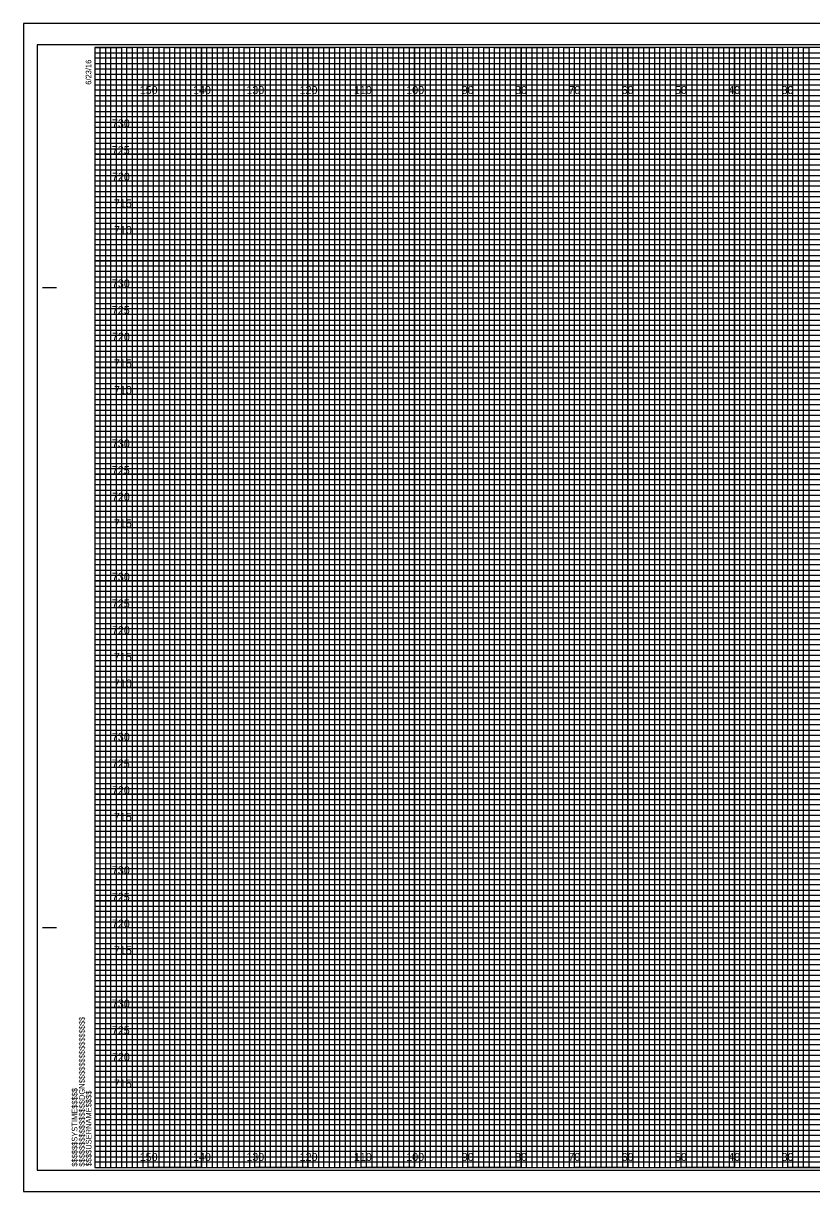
# Model space of a CAD drawing. Extents: x -13 to 323, y -5 to 434.
# Drawn here: x -13.4 to 134.5, y -4.5 to 214.5 of the extents above; entities that cross this region are included whole.
import ezdxf

# ---------------------------------------------------------------- set-up
doc = ezdxf.new("R2010")
doc.units = 0
for name, color, linetype in [('Exist Cross Section Cell', 7, 'Continuous'), ('Prop CMT Pvmt Course 1', 7, 'Continuous'), ('Prop CMT Pvmt Course 2', 7, 'Continuous'), ('Prop CMT Pvmt Course 3', 7, 'Continuous'), ('Prop CMT Pvmt Surface Shoulder', 7, 'Continuous'), ('Prop CMT Shld Paved Course 1', 7, 'Continuous'), ('Prop CMT Shld Paved Course 2', 7, 'Continuous'), ('Prop CMT Shld Paved Course 3', 7, 'Continuous'), ('Prop CMT Slope Grass', 7, 'Continuous'), ('Prop CMT Subgrade Earthwork', 7, 'Continuous'), ('Scratch_Level_1', 7, 'Continuous')]:
    doc.layers.add(name, color=color, linetype=linetype)

msp = doc.modelspace()

# ---------------------------------------------------------------- linework, layer by layer
at = {"layer": 'Prop CMT Pvmt Course 1'}
msp.add_lwpolyline([(-10.8, -0.5), (322.4, -0.5), (322.4, 210.5), (-10.8, 210.5)], close=True, dxfattribs=at)
at = {"layer": 'Prop CMT Pvmt Course 2'}
for p, q in [((10, 0), (10, 210)), ((20, 0), (20, 210)), ((30, 0), (30, 210)), ((40, 0), (40, 210)), ((50, 0), (50, 210)), ((60, 0), (60, 210)), ((70, 0), (70, 210)), ((80, 0), (80, 210)), ((90, 0), (90, 210)), ((100, 0), (100, 210)), ((110, 0), (110, 210)), ((120, 0), (120, 210)), ((130, 0), (130, 210)), ((0, 200), (320, 200)), ((0, 190), (320, 190)), ((0, 180), (320, 180)), ((0, 170), (320, 170)), ((0, 160), (320, 160)), ((0, 150), (320, 150)), ((0, 140), (320, 140)), ((0, 130), (320, 130)), ((0, 120), (320, 120)), ((0, 110), (320, 110)), ((0, 100), (320, 100)), ((0, 90), (320, 90)), ((0, 80), (320, 80)), ((0, 70), (320, 70)), ((0, 60), (320, 60)), ((0, 50), (320, 50)), ((0, 40), (320, 40)), ((0, 30), (320, 30)), ((0, 20), (320, 20)), ((0, 10), (320, 10))]:
    msp.add_line(p, q, dxfattribs=at)
at = {"layer": 'Prop CMT Pvmt Course 3'}
for p, q in [((323.3, 214.5), (-13.4, 214.5)), ((-13.4, 214.5), (-13.4, -4.5)), ((-13.4, -4.5), (323.3, -4.5))]:
    msp.add_line(p, q, dxfattribs=at)
at = {"layer": 'Prop CMT Pvmt Surface Shoulder'}
msp.add_lwpolyline([(-13.4, -4.5), (323.3, -4.5), (323.3, 214.5), (-13.4, 214.5)], close=True, dxfattribs=at)
at = {"layer": 'Prop CMT Shld Paved Course 1'}
for points in [[(0, 210), (5, 210), (5, 0), (15, 0), (15, 210), (25, 210), (25, 0), (35, 0), (35, 210), (45, 210), (45, 0), (55, 0), (55, 210), (65, 210), (65, 0), (75, 0), (75, 210), (85, 210), (85, 0), (95, 0), (95, 210), (105, 210), (105, 0), (115, 0), (115, 210), (125, 210), (125, 0), (135, 0)], [(0, 205), (275, 205)], [(0, 185), (320, 185), (320, 195), (0, 195)], [(0, 165), (320, 165), (320, 175), (0, 175)], [(0, 145), (320, 145), (320, 155), (0, 155)], [(0, 125), (320, 125), (320, 135), (0, 135)], [(0, 105), (320, 105), (320, 115), (0, 115)], [(0, 85), (320, 85), (320, 95), (0, 95)], [(0, 65), (320, 65), (320, 75), (0, 75)], [(0, 45), (320, 45), (320, 55), (0, 55)], [(0, 25), (320, 25), (320, 35), (0, 35)], [(0, 5), (320, 5), (320, 15), (0, 15)]]:
    msp.add_lwpolyline(points, dxfattribs=at)
at = {"layer": 'Prop CMT Shld Paved Course 2'}
for p, q in [((0, 209), (260, 209)), ((260, 207.98), (0, 207.98)), ((0, 207.98), (0, 207)), ((0, 207), (260, 207)), ((260, 205.89), (0, 205.89)), ((0, 205.89), (0, 204)), ((0, 204), (320, 204))]:
    msp.add_line(p, q, dxfattribs=at)
for points in [[(0, 203), (270, 203), (320, 203), (320, 202), (0, 202)], [(0, 201), (320, 201), (320, 199), (0, 199)], [(0, 198), (320, 198), (320, 197), (0, 196.98)], [(0, 196), (320, 196), (320, 194), (0, 194)], [(0, 193), (320, 193), (320, 192), (0, 192)], [(0, 191), (320, 191), (320, 189), (0, 189)], [(0, 188), (320, 188), (320, 187), (0, 187)], [(0, 186), (320, 186), (320, 184), (0, 184)], [(0, 183), (320, 183), (320, 182), (0, 182)], [(0, 181), (320, 181), (320, 179), (0, 179)], [(0, 178), (320, 178), (320, 177), (0, 177)], [(0, 176), (320, 176), (320, 173.95), (320, 173), (320, 172), (0, 172)], [(0, 174), (320, 174), (320, 173), (0, 173)], [(0, 171), (320, 171), (320, 169), (0, 169.03)], [(0, 169.03), (320, 169), (320, 168), (0, 168)], [(0, 167), (320, 167), (320, 166), (0, 166)], [(0, 164), (320, 164), (320, 163), (0, 163)], [(0, 162), (320, 162), (320, 161), (0, 161)], [(-0.07, 158.89), (320, 158.89), (320, 157.88), (-0.07, 157.88)], [(0, 157), (320, 157), (320, 156), (0, 156)], [(0, 154), (320, 154), (320, 153), (0, 153)], [(0, 152), (320, 152), (320, 151), (0, 151)], [(0, 149), (320, 149), (320, 148), (0, 148)], [(0, 147), (320, 147), (320, 146), (0, 146)], [(0, 144), (320, 144), (320, 143), (0, 143)], [(0, 142), (320, 142), (320, 141), (0, 141)], [(0, 139), (320, 139), (319.99, 137.98), (0, 138)], [(0, 137), (320, 137), (320, 136), (0, 136)], [(0, 134), (320, 134), (320, 133), (0, 133)], [(0, 132), (320, 132), (320, 131), (0, 131)], [(0, 129), (320, 129), (320, 128), (0, 128)], [(0, 127), (320, 127), (320, 126), (0, 126)], [(0, 124), (320, 124), (320, 123), (0, 123)], [(0, 122), (320, 122), (320, 121), (0, 121)], [(0, 119), (320, 119), (320, 118), (0, 118)], [(0, 116.99), (320.07, 116.91), (320, 116), (0, 116)], [(0, 114), (320, 114), (320, 113), (0, 113)], [(0, 112), (320, 112), (320, 111), (0, 111)], [(0, 109), (320, 109), (320, 108), (0, 108)], [(0, 107), (320, 107), (320, 106), (0, 106)], [(0, 104), (320, 104), (320, 103), (0, 103)], [(0, 102), (320, 102), (320, 101), (0, 101)], [(0, 99), (320, 99), (320, 98), (0, 98)], [(0, 97), (320, 97), (320, 96), (0, 96)], [(0, 94), (320, 94), (320, 93), (0, 93)], [(0, 92), (320, 92), (320, 91), (0, 91)], [(0, 89), (320, 89), (320, 88), (0, 88)], [(0, 87), (320, 87), (320, 86), (0, 86)], [(0, 84), (320, 84), (320, 83), (0, 83)], [(0, 82), (320, 82), (320, 81), (0, 81)], [(0, 79), (320, 79), (319.99, 77.98), (0, 78)], [(0, 77), (320, 77), (320, 76), (0, 76)], [(0, 74), (320, 74), (320, 73), (0, 73)], [(0, 72), (320, 72), (320, 71), (0, 71)], [(0, 69), (320, 69), (320, 68), (0, 68)], [(0, 67), (320, 67), (320, 66), (0, 66)], [(0, 64), (320, 64), (320, 63), (0, 63)], [(0, 62), (320, 62), (320, 61), (0, 61)], [(0, 59), (320, 59), (320, 58), (0, 58)], [(0, 56.99), (320.07, 56.91), (320, 56), (0, 56)], [(0, 54), (320, 54), (320, 53), (0, 53)], [(0, 52), (320, 52), (320, 51), (0, 51)], [(0, 49), (320, 49), (320, 48), (0, 48)], [(0, 47), (320, 47), (320, 46), (0, 46)], [(0, 44), (320, 44), (320, 43), (0, 43)], [(0, 42), (320, 42), (320, 41), (0, 41)], [(0, 39), (320, 39), (320, 38), (0, 38)], [(0, 37), (320, 37), (320, 36), (0, 36)], [(0, 34), (320, 34), (320, 33), (0, 33)], [(0, 32), (320, 32), (320, 31), (0, 31)], [(0, 29), (320, 29), (320, 28), (0, 28)], [(0, 27), (320, 27), (320, 26), (0, 26)], [(0, 24), (320, 24), (320, 23), (0, 23)], [(0, 22), (320, 22), (320, 21), (0, 21)], [(0, 19), (320, 19), (320, 18), (0, 18)], [(0, 17), (320, 17), (320, 16), (0, 16)], [(0, 14), (320, 14), (320, 13), (0, 13)], [(0, 12), (320, 12), (320, 11), (0, 11)], [(0, 9), (320, 9), (320, 8), (0, 8)], [(0, 7), (320, 7), (320, 6), (0, 6)], [(0, 4), (320, 4), (320, 3), (0, 3)], [(0, 2), (320, 2), (320, 1), (0, 1)]]:
    msp.add_lwpolyline(points, dxfattribs=at)
at = {"layer": 'Prop CMT Shld Paved Course 3'}
for p, q in [((-9.8, 165), (-7.3, 165)), ((-9.7, 165), (-7.2, 165)), ((-9.8, 45), (-7.3, 45)), ((-9.7, 45), (-7.2, 45)), ((0, 0), (0, 0)), ((0, 0), (0, 0)), ((0, 0), (0, 0)), ((0, 0), (0, 0)), ((0, 0), (0, 0)), ((0, 0), (0, 0)), ((0, 0), (0, 0))]:
    msp.add_line(p, q, dxfattribs=at)
msp.add_lwpolyline([(320, 210), (0, 210), (0, 0), (320, 0)], close=True, dxfattribs=at)
at = {"layer": 'Prop CMT Subgrade Earthwork'}
for points in [[(0, 0), (1, 0), (1, 210), (2, 210), (2, 0)], [(2, 0), (3, 0), (3, 210), (4, 210), (4, 0)], [(5, 0), (6, 0), (6, 210), (7, 210), (7, 0)], [(7, 0), (8, 0), (8, 210), (9, 210), (9, 0)], [(10, 0), (11, 0), (11, 210), (12, 210), (12, 0)], [(12, 0), (13, 0), (13, 210), (14, 210), (14, 0)], [(15, 0), (16, 0), (16, 210), (17, 210), (17, 0)], [(17, 0), (18, 0), (18, 210), (19, 210), (19, 0)], [(20, 0), (21, 0), (21, 210), (22, 210), (22, 0)], [(22, 0), (23, 0), (23, 210), (24, 210), (24, 0)], [(25, 0), (26, 0), (26, 210), (27, 210), (27, 0)], [(27, 0), (28, 0), (28, 210), (29, 210), (29, 0)], [(30, 0), (31, 0), (31, 210), (32, 210), (32, 0)], [(32, 0), (33, 0), (33, 210), (34, 210), (34, 0)], [(35, 0), (36, 0), (36, 210), (37, 210), (37, 0)], [(37, 0), (38, 0), (38, 210), (39, 210), (39, 0)], [(40, 0), (41, 0), (41, 210), (42, 210), (42, 0)], [(42, 0), (43, 0), (43, 210), (44, 210), (44, 0)], [(45, 0), (46, 0), (46, 210), (47, 210), (47, 0)], [(47, 0), (48, 0), (48, 210), (49, 210), (49, 0)], [(50, 0), (51, 0), (51, 210), (52, 210), (52, 0)], [(52, 0), (53, 0), (53, 210), (54, 210), (54, 0)], [(55, 0), (56, 0), (56, 210), (57, 210), (57, 0)], [(57, 0), (58, 0), (58, 210), (59, 210), (59, 0)], [(60, 0), (61, 0), (61, 210), (62, 210), (62, 0)], [(62, 0), (63, 0), (63, 210), (64, 210), (64, 0)], [(65, 0), (66, 0), (66, 210), (67, 210), (67, 0)], [(67, 0), (68, 0), (68, 210), (69, 210), (69, 0)], [(70, 0), (71, 0), (71, 210), (72, 210), (72, 0)], [(72, 0), (73, 0), (73, 210), (74, 210), (74, 0)], [(75, 0), (76, 0), (76, 210), (77, 210), (77, 0)], [(77, 0), (78, 0), (78, 210), (79, 210), (79, 0)], [(80, 0), (81, 0), (81, 210), (82, 210), (82, 0)], [(82, 0), (83, 0), (83, 210), (84, 210), (84, 0)], [(85, 0), (86, 0), (86, 210), (87, 210), (87, 0)], [(87, 0), (88, 0), (88, 210), (89, 210), (89, 0)], [(90, 0), (91, 0), (91, 210), (92, 210), (92, 0)], [(92, 0), (93, 0), (93, 210), (94, 210), (94, 0)], [(95, 0), (96, 0), (96, 210), (97, 210), (97, 0)], [(97, 0), (98, 0), (98, 210), (99, 210), (99, 0)], [(100, 0), (101, 0), (101, 210), (102, 210), (102, 0)], [(102, 0), (103, 0), (103, 210), (104, 210), (104, 0)], [(105, 0), (106, 0), (106, 210), (107, 210), (107, 0)], [(107, 0), (108, 0), (108, 210), (109, 210), (109, 0)], [(110, 0), (111, 0), (111, 210), (112, 210), (112, 0)], [(112, 0), (113, 0), (113, 210), (114, 210), (114, 0)], [(115, 0), (116, 0), (116, 210), (117, 210), (117, 0)], [(117, 0), (118, 0), (118, 210), (119, 210), (119, 0)], [(120, 0), (121, 0), (121, 210), (122, 210), (122, 0)], [(122, 0), (123, 0), (123, 210), (124, 210), (124, 0)], [(125, 0), (126, 0), (126, 210), (127, 210), (127, 0)], [(127, 0), (128, 0), (128, 210), (129, 210), (129, 0)], [(130, 0), (131, 0), (131, 210), (132, 210), (132, 0)], [(132, 0), (133, 0), (133, 210), (134, 210), (134, 0)]]:
    msp.add_lwpolyline(points, dxfattribs=at)
at = {"layer": 'Scratch_Level_1'}
for p, q in [((10, 210), (0, 210)), ((10, 0), (10, 210)), ((30, 210), (20, 210)), ((20, 210), (20, 0)), ((30, 0), (30, 210)), ((50, 210), (40, 210)), ((40, 210), (40, 0)), ((50, 0), (50, 210)), ((70, 210), (60, 210)), ((60, 210), (60, 0)), ((70, 0), (70, 210)), ((90, 210), (80, 210)), ((80, 210), (80, 0)), ((90, 0), (90, 210)), ((110, 210), (100, 210)), ((100, 210), (100, 0)), ((110, 0), (110, 210)), ((130, 210), (120, 210)), ((120, 210), (120, 0)), ((130, 0), (130, 210)), ((20, 0), (10, 0)), ((40, 0), (30, 0)), ((60, 0), (50, 0)), ((80, 0), (70, 0)), ((100, 0), (90, 0)), ((120, 0), (110, 0)), ((140, 0), (130, 0))]:
    msp.add_line(p, q, dxfattribs=at)
for points in [[(0, 200), (320, 200), (320, 190), (0, 190)], [(0, 180), (320, 180), (320, 170), (0, 170)], [(0, 160), (320, 160), (320, 150), (0, 150)], [(0, 140), (320, 140), (320, 130), (0, 130)], [(0, 120), (320, 120), (320, 110), (0, 110)], [(0, 100), (320, 100), (320, 90), (0, 90)], [(0, 80), (320, 80), (320, 70), (0, 70)], [(0, 60), (320, 60), (320, 50), (0, 50)], [(0, 40), (320, 40), (320, 30), (0, 30)], [(0, 20), (320, 20), (320, 10), (0, 10)]]:
    msp.add_lwpolyline(points, dxfattribs=at)

# ---------------------------------------------------------------- texts
at = {"layer": 'Exist Cross Section Cell'}
for s, p in [('150', (8.44, 201.25)), ('140', (18.44, 201.25)), ('130', (28.44, 201.25)), ('120', (38.44, 201.25)), ('110', (48.62, 201.25)), ('100', (58.44, 201.25)), ('90', (68.86, 201.25)), ('80', (78.86, 201.25)), ('70', (88.86, 201.25)), ('60', (98.86, 201.25)), ('50', (108.86, 201.25)), ('40', (118.86, 201.25)), ('30', (128.86, 201.25)), ('150', (8.44, 1.25)), ('140', (18.44, 1.25)), ('130', (28.44, 1.25)), ('120', (38.44, 1.25)), ('110', (48.62, 1.25)), ('100', (58.44, 1.25)), ('90', (68.86, 1.25)), ('80', (78.86, 1.25)), ('70', (88.86, 1.25)), ('60', (98.86, 1.25)), ('50', (108.86, 1.25)), ('40', (118.86, 1.25)), ('30', (128.86, 1.25))]:
    msp.add_text(s, height=1.5, dxfattribs=at).set_placement(p)
at = {"layer": 'Prop CMT Shld Paved Course 3'}
for s, p in [('6/23/16', (-0.65, 203)), ('$$$$$$$$$$$$$$$$DGN$$$$$$$$$$$$$$$$', (-1.88, 0.18)), ('$$$$$$SYSTIME$$$$$', (-3.26, 0.18)), ('$$$$USERNAME$$$$', (-0.62, 0.23))]:
    msp.add_text(s, height=1.05, rotation=90, dxfattribs=at).set_placement(p)
at = {"layer": 'Prop CMT Slope Grass'}
for s, p in [('730', (3.22, 195)), ('725', (3.21, 190)), ('720', (3.23, 185)), ('715', (3.59, 180)), ('710', (3.61, 175)), ('730', (3.22, 165)), ('725', (3.21, 160)), ('720', (3.23, 155)), ('715', (3.59, 150)), ('710', (3.61, 145)), ('730', (3.22, 135)), ('725', (3.21, 130)), ('720', (3.23, 125)), ('715', (3.59, 120)), ('730', (3.22, 110)), ('725', (3.21, 105)), ('720', (3.23, 100)), ('715', (3.59, 95)), ('710', (3.61, 90)), ('730', (3.22, 80)), ('725', (3.21, 75)), ('720', (3.23, 70)), ('715', (3.59, 65)), ('730', (3.22, 55)), ('725', (3.21, 50)), ('720', (3.23, 45)), ('715', (3.59, 40)), ('730', (3.22, 30)), ('725', (3.21, 25)), ('720', (3.23, 20)), ('715', (3.59, 15))]:
    msp.add_text(s, height=1.5, dxfattribs=at).set_placement(p)

doc.saveas('drawing.dxf')
